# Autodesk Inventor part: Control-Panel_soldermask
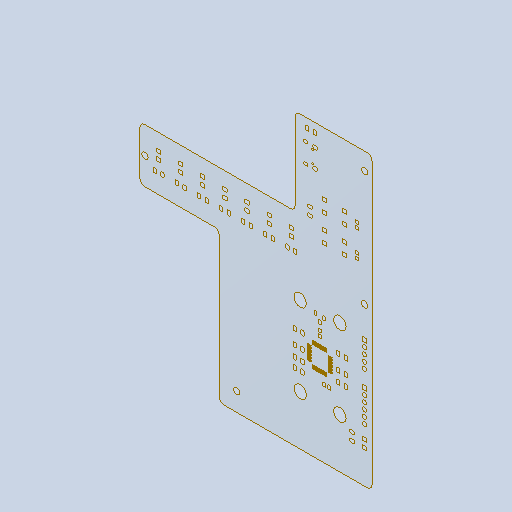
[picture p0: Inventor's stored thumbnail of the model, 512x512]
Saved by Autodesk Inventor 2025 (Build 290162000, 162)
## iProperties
Created: 2026-09
Part Number: Control-Panel_soldermask
Material: Generic
Document SubType Name: Modeling
Designer: Leonardo
Density: 1 g/cm^3
Appearance: Default
Author: Leonardo
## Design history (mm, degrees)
feature "Composite1"
body "Srf1"
